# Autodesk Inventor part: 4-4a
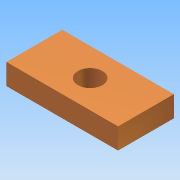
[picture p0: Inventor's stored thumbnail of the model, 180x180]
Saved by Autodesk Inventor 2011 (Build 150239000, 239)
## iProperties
Created: 2014-03
Part Number: 4-4a
Document SubType Name: Modeling
Designer: Administrator
Density: 1 g/cm^3
Author: Administrator
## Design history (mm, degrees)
sketch "草图1"
  geometry: L1 (-40, 20)-(40, 20); L2 (40, 20)-(40, -20); L3 (40, -20)-(-40, -20); L4 (-40, -20)-(-40, 20); 3 further points
  constraints: 8 end point, 2 midpoint, 2 parallel, 1 horizontal, 1 horizontal alignment, 1 perpendicular, 1 vertical alignment
  dimensions: "d0" = 80 distance of L1.start L1.end; "d1" = 40 distance of L3.end L1.start
extrude "拉伸1" new body sketch "草图1" distance "d2" = 15; taper "d3" = 0 deg
hole "Hole1" diameter "d6" = 17.6; stored, may be unused: countersink angle "d10" = 90 deg, drill point angle "d12" = 118 deg; dims "d4" = 20, "d5" = 40, "d7" = 6, "d8" = 4, "d9" = 2, "d11" = 8
node "实体1"
